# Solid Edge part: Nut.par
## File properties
Author: Sarvanan
Template: sync iso part.par
Last saved by: CADCIM
Revision: 11
Application: Solid Edge
Accuracy: 0.990
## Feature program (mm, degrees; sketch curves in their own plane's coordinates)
sketch for "Hole_1" plane through (21.0838, 43.6973, 8) normal (0, 0, 1) x-axis (1, 0, 0)
  hole centre (-1.3414, 0.2221) bore radius 6
hole "Hole_1" diameter 12 through
pattern "unnamed Pattern 1" of "Hole_1"
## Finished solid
Body 1: solid body, 21 faces, 56 edges, 36 vertices.
  Faces by surface: spun 12, plane 8, cylinder 1
  Edges by curve: circle 18, line 18, intersection 17, spline 3
Bounding box of the edges (mm; curved faces can reach further): 30.022 x 26.000 x 12.000, from (4.7313, 30.9194, 0) to (34.7535, 56.9194, 12).
Cylindrical faces by radius (mm): R6 x1
Planar faces by outward normal: +y 1, +z 1, -y 1, -z 1, oblique 4
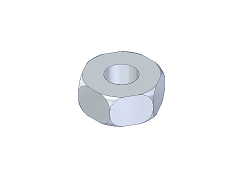
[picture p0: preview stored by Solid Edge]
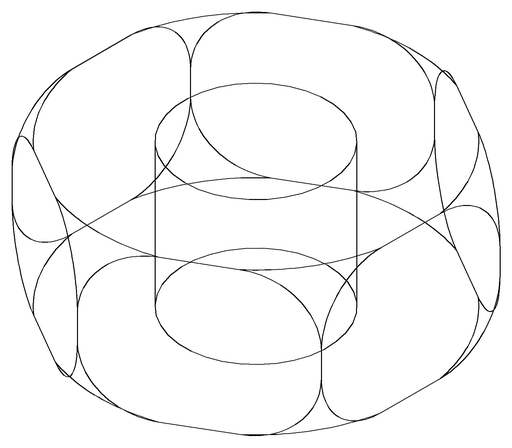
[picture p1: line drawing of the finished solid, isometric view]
